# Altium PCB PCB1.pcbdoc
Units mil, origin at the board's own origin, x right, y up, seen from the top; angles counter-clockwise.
Board outline 3930 x 3935 mil, 2 copper layers (Top Layer, Bottom Layer); 17 components, 42 nets, 112 pads, 12 vias.
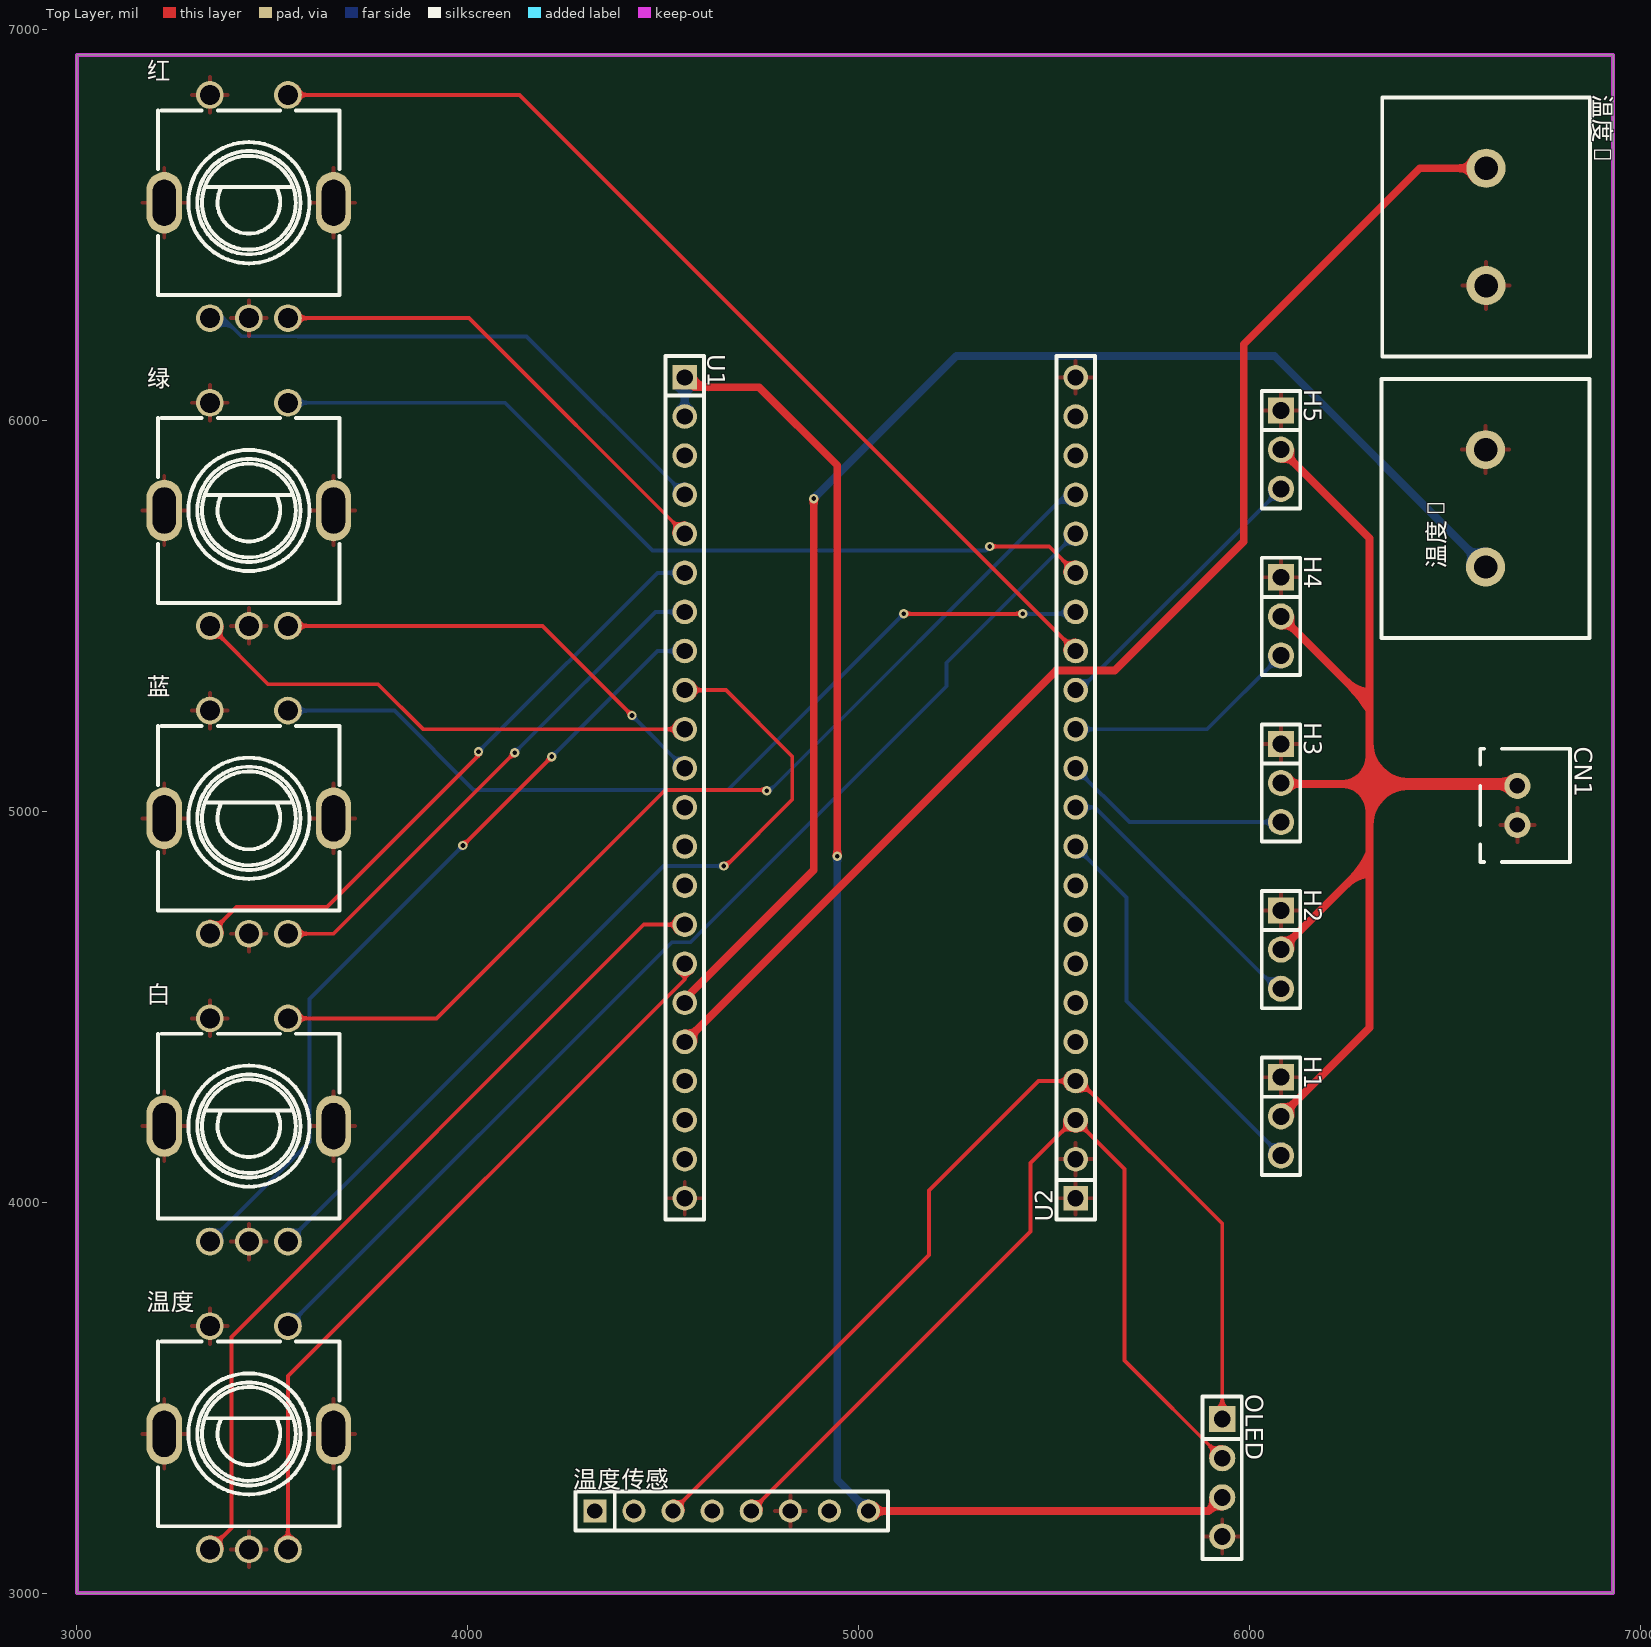
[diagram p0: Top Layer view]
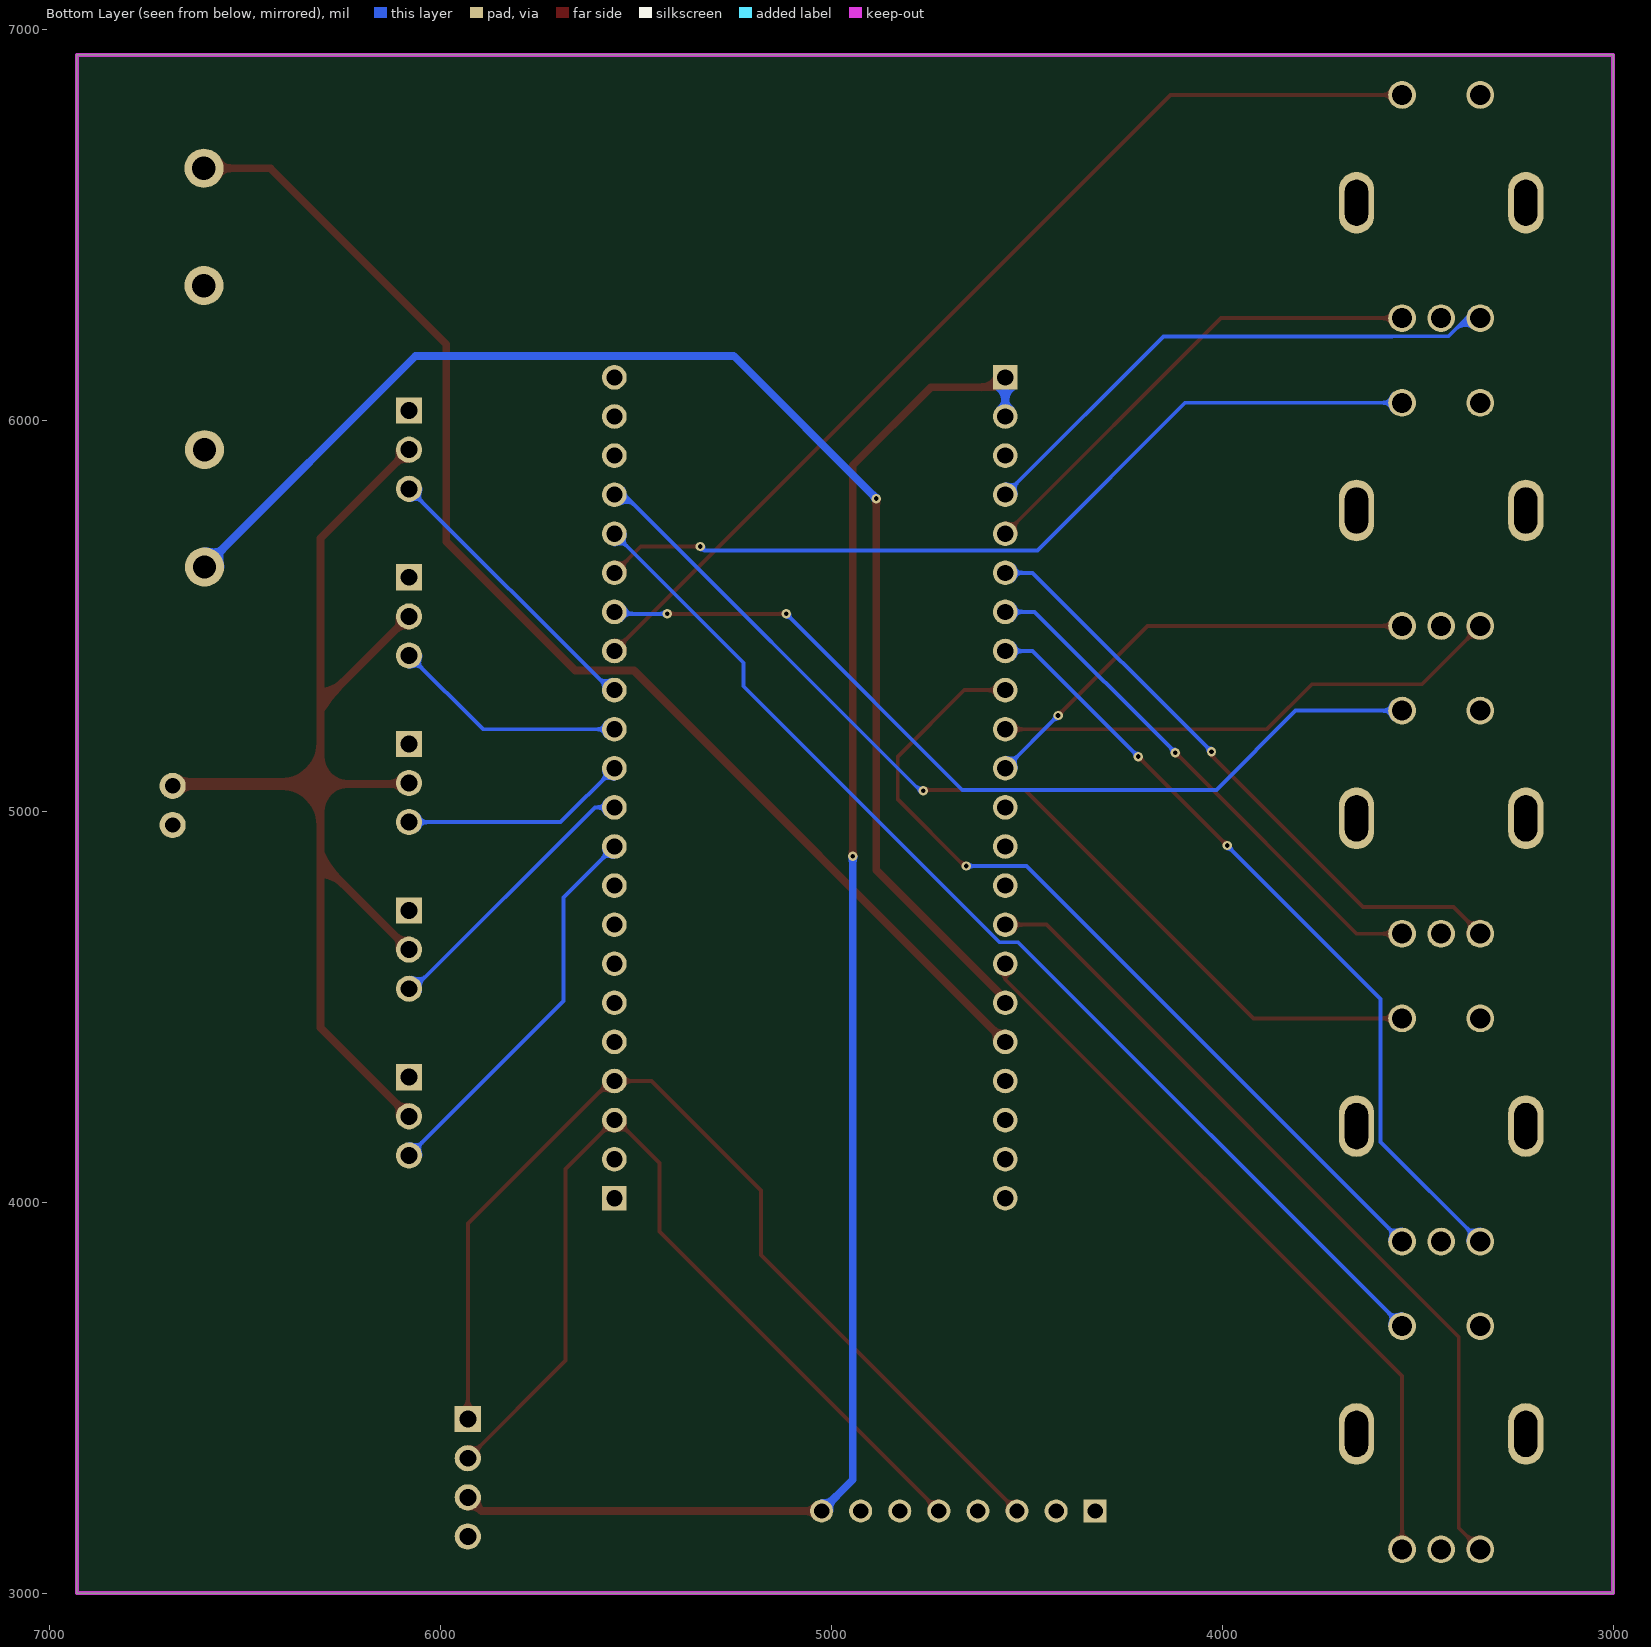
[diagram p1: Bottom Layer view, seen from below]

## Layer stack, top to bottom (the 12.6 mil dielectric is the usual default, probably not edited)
Top Layer: signal copper (thickness not stored)
Dielectric: dielectric 12.6, FR-4, Dk 4.8
Bottom Layer: signal copper (thickness not stored)

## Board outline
3000,6935 6930,6935 6930,3000 3000,3000

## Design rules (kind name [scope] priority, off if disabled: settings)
BoardOutlineClearance copperThickness1oz [All] p0: genericclearance=10 ignorepadtopadclearanceinfootprint=FALSE except(0: Arc-SplitContinuation Track-SplitContinuation SMDPad-SplitContinuation THPad-SplitContinuation Via-SplitContinuation Fill-SplitContinuation Poly-SplitContinuation Region-SplitContinuation Text-SplitContinuation; 6: Track-CutoutEdge SMDPad-CutoutEdge THPad-CutoutEdge Via-CutoutEdge Region-CutoutEdge; 11.8: Track-OutlineEdge SMDPad-OutlineEdge THPad-OutlineEdge Via-OutlineEdge Fill-OutlineEdge Region-OutlineEdge Poly-OutlineEdge Text-OutlineEdge Fill-CutoutEdge)
BoardOutlineClearance copperThickness2oz [All] p0: genericclearance=10 ignorepadtopadclearanceinfootprint=FALSE except(0: Arc-SplitContinuation Track-SplitContinuation SMDPad-SplitContinuation THPad-SplitContinuation Via-SplitContinuation Fill-SplitContinuation Poly-SplitContinuation Region-SplitContinuation Text-SplitContinuation; 6: Track-CutoutEdge SMDPad-CutoutEdge THPad-CutoutEdge Via-CutoutEdge Region-CutoutEdge; 11.8: Track-OutlineEdge SMDPad-OutlineEdge THPad-OutlineEdge Via-OutlineEdge Fill-OutlineEdge Region-OutlineEdge Poly-OutlineEdge Text-OutlineEdge Fill-CutoutEdge)
Clearance copperThickness1oz [(InNet('0') OR InNet('1') OR InNet('2') OR InNet('3') OR InNet('4') OR InNet('5') OR InNet('6') OR InNet('7') OR InNet('8') OR InNet('9') OR InNet('10') OR InNet('11') OR InNet('12') OR InNet('13') OR InNet('14') OR InNet('15') OR InNet('16') OR InNet('17') OR InNet('18') OR InNet('21') OR InNet('35') OR InNet('36') OR InNet('37') OR InNet('38') OR InNet('39') OR InNet('40') OR InNet('41') OR InNet('42') OR InNet('45') OR InNet('46') OR InNet('47') OR InNet('48') OR InNet('SDA') OR InNet('SCL') OR InNet('GND') OR InNet('3.3V') OR InNet('RST') OR InNet('5VIN') OR InNet('RX') OR InNet('TX') OR InNet('CS') OR InNet('+5V'))] p1: gap=7 ignorepadtopadclearanceinfootprint=FALSE except(4: Track-Track; 6: Track-SMDPad SMDPad-SMDPad Track-THPad SMDPad-THPad THPad-THPad Track-Via SMDPad-Via THPad-Via Via-Via SMDPad-Fill THPad-Fill Via-Fill Fill-Fill Track-Region SMDPad-Region THPad-Region Via-Region Region-Region Track-Poly SMDPad-Poly THPad-Poly Via-Poly Fill-Poly Region-Poly Poly-Poly Track-Text SMDPad-Text THPad-Text Via-Text Fill-Text Region-Text Poly-Text Text-Text; 6.9: Track-Hole SMDPad-Hole THPad-Hole Via-Hole Fill-Hole Region-Hole Poly-Hole Text-Hole Sheet-Hole; 11.8: Track-Fill Fill-Region Track-Sheet SMDPad-Sheet THPad-Sheet Via-Sheet Fill-Sheet Region-Sheet Poly-Sheet Text-Sheet)
Clearance copperThickness2oz [All] p1: gap=7 ignorepadtopadclearanceinfootprint=FALSE except(6: Track-SMDPad SMDPad-SMDPad Track-THPad SMDPad-THPad THPad-THPad Track-Via SMDPad-Via THPad-Via Via-Via SMDPad-Fill THPad-Fill Via-Fill Fill-Fill Track-Region SMDPad-Region THPad-Region Via-Region Region-Region Track-Poly SMDPad-Poly THPad-Poly Via-Poly Fill-Poly Region-Poly Poly-Poly Track-Text SMDPad-Text THPad-Text Via-Text Fill-Text Region-Text Poly-Text Text-Text; 6.9: Track-Hole SMDPad-Hole THPad-Hole Via-Hole Fill-Hole Region-Hole Poly-Hole Text-Hole Sheet-Hole; 8: Track-Track; 11.8: Track-Fill Fill-Region Track-Sheet SMDPad-Sheet THPad-Sheet Via-Sheet Fill-Sheet Region-Sheet Poly-Sheet Text-Sheet)
DiffPairsRouting differentialPair [All] p1: maxuncoupledlength=10 minlimit=6 maxlimit=6 mostfreqgap=6 toplayer_minwidth=5 toplayer_prefwidth=10 toplayer_maxwidth=100 bottomlayer_minwidth=5 bottomlayer_prefwidth=10 bottomlayer_maxwidth=100
PasteMaskExpansion pasteMaskExpansion [All] p1: expansion=0
PlaneConnect innerPlane [All] p1: planeconnectstyle=Relief reliefexpansion=20 reliefentries=4 reliefconductorwidth=10 reliefairgap=10
PolygonConnect copperRegion [All] p1: connectstyle=Relief reliefentries=4 reliefconductorwidth=10 polygonreliefangle="90 Angle" airgapwidth=10
RoutingVias viaSize [All] p1: viastyle="Through Hole" holewidth=12.0078 minholewidth=11.811 maxholewidth=248.0314 width=24.0158 minwidth=19.685 maxwidth=393.7008
SolderMaskExpansion solderMaskExpansion [All] p1: useseparateexpansions=TRUE expansion=2 expansionbottom=2
Width copperThickness1oz [All] p1: maxlimit=100 minlimit=5 preferedwidth=10
Width copperThickness2oz [All] p1: maxlimit=100 minlimit=8 preferedwidth=10

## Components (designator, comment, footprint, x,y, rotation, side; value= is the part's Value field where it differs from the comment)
CN1 "B2B-XH-A(LF)(SN)" CONN-TH_B2B-XH-A-LF-SN 6685,5015 r270 top
H1 "PZ254V-11-03P" HDR-TH_3P-P2.54-V-M 6080.28,4219.75 r270 top
H2 "PZ254V-11-03P" HDR-TH_3P-P2.54-V-M 6080.28,4646.06 r270 top
H3 "PZ254V-11-03P" HDR-TH_3P-P2.54-V-M 6080.28,5072.38 r270 top
H4 "PZ254V-11-03P" HDR-TH_3P-P2.54-V-M 6080.28,5498.69 r270 top
H5 "PZ254V-11-03P" HDR-TH_3P-P2.54-V-M 6080.28,5925 r270 top
OLED "HDR-F_2.54_1x4P" HDR-TH_4P-P2.54-V-F 5930,3295 r270 top
U1 "ZX-PM2.54-1-22PY" HDR-TH_22P-P2.54-V-F 4555,5060 r270 top
U2 "ZX-PM2.54-1-22PY" HDR-TH_22P-P2.54-V-F 5555,5060 r90 top
温度 "EC11E15244G1" SW-TH_EC11E15244G1 3440,3397.4 r0 top
温度1 "WJ25C-B-7.62-2P" CONN-TH_2P-P7.62_WJ25C-B-7.62-2P 6603.54,5775 r90 top
温度2 "WJ25C-B-7.62-2P" CONN-TH_2P-P7.62_WJ25C-B-7.62-2P 6605,6495 r270 top
温度传感 "PZ254V-11-08P" HDR-TH_8P-P2.54-V-M 4675,3210 r0 top
白 "EC11E15244G1" SW-TH_EC11E15244G1 3440,4184.8 r0 top
红 "5" SW-TH_EC11E15244G1 3440,6547.01 r0 top
绿 "EC11E15244G1" SW-TH_EC11E15244G1 3440,5759.61 r0 top
蓝 "EC11E15244G1" SW-TH_EC11E15244G1 3440,4972.2 r0 top

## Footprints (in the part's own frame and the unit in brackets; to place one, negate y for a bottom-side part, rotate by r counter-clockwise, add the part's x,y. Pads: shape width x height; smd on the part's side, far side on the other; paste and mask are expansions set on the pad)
CONN-TH_2P-P7.62_WJ25C-B-7.62-2P [mil]
  round 100 hole 60: 1(-150.1,0) 2(150.1,0)
  silkscreen extent -331,-266 331,266
CONN-TH_B2B-XH-A-LF-SN [mm]
  round 1.7 hole 1: 1(1.27,0) 2(-1.27,0)
  silkscreen extent -3.68,-2.41 3.68,3.43
HDR-TH_3P-P2.54-V-M [mm]
  rect 1.7x1.7 hole 1.1: 1(-2.54,0)
  round 1.7 hole 1.1: 2(0,0) 3(2.54,0)
  silkscreen extent -3.81,-1.25 3.81,1.25
HDR-TH_4P-P2.54-V-F [mm]
  rect 1.7x1.7 hole 1.1: 1(-3.81,0)
  round 1.7 hole 1.1: 2(-1.27,0) 3(1.27,0) 4(3.81,0)
  silkscreen extent -5.29,-1.27 5.29,1.27
HDR-TH_8P-P2.54-V-M [mm]
  rect 1.5x1.5 hole 1: 1(-8.89,0)
  round 1.5 hole 1: 2(-6.35,0) 3(-3.81,0) 4(-1.27,0) 5(1.27,0) 6(3.81,0) 7(6.35,0) 8(8.89,0)
  silkscreen extent -10.16,-1.27 10.16,1.27
HDR-TH_22P-P2.54-V-F [mm]
  rect 1.6x1.6 hole 1.05: 1(-26.67,0)
  round 1.6 hole 1.05: 2(-24.13,0) 3(-21.59,0) 4(-19.05,0) 5(-16.51,0) 6(-13.97,0) 7(-11.43,0) 8(-8.89,0) 9(-6.35,0) 10(-3.81,0) 11(-1.27,0) 12(1.27,0) 13(3.81,0) 14(6.35,0) 15(8.89,0) 16(11.43,0) 17(13.97,0) 18(16.51,0) 19(19.05,0) 20(21.59,0) 21(24.13,0) 22(26.67,0)
  silkscreen extent -28.06,-1.25 28.06,1.25
SW-TH_EC11E15244G1 [mm]
  oval 2.3x4 hole 1.5 slot 3 at 90 deg: 6(5.5,0.25) 7(-5.5,0.25)
  round 1.8 hole 1.3: A(-2.54,-7.25) B(2.54,-7.25) C(0,-7.25) D(-2.54,7.25) E(2.54,7.25)
  silkscreen extent -5.9,-5.75 5.9,6.25

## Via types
v1: diameter 24.02, hole 12.01, Top Layer to Bottom Layer, 12 vias

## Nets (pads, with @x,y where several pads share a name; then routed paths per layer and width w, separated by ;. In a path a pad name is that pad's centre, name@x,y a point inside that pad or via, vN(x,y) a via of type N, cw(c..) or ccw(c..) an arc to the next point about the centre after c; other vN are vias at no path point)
0: U2.9
1: U2.19 白.E | length 2572
  Top Layer w10: 白.E 3920.24,4470.24 4505,5055 4762.5,5055 v1(4765,5052.5)
  Bottom Layer w10: v1(4765,5052.5) 4772.5,5052.5 5530,5810 U2.19
2: U2.18 温度.E | length 2889.9
  Bottom Layer w10: 温度.E 4522.16,4665 4570.08,4665 5225,5319.92 5225,5380 U2.18
3: U1.13
3.3V: OLED.3 U1.1 U1.2 温度传感.8 | length 4210.8
  Top Layer w20: U1.1 4580,6085 4745,6085 4945,5885 v1(4945,4885) ; 温度传感.8 5895,3210 OLED.3
  Bottom Layer w20: U1.2 U1.1 ; v1(4945,4885) 4945,3290 温度传感.8
4: U1.4 红.A | length 1402.1
  Bottom Layer w10: 红.A 3374.35,6261.57 3420.77,6215.16 3564.84,6215.16 3565,6215 4150,6215 U1.4
5: U1.5 红.B | length 1243.5
  Top Layer w10: 红.B 4003.43,6261.57 U1.5
5VIN: U1.21
6: U1.6 蓝.A | length 1603.3
  Top Layer w10: 蓝.A 3408.23,4755 3640,4755 4027.5,5142.5 v1(4027.5,5152.5)
  Bottom Layer w10: v1(4027.5,5152.5) 4485,5610 U1.6
7: U1.7 蓝.B | length 1356
  Top Layer w10: 蓝.B 3656.77,4686.77 v1(4120,5150)
  Bottom Layer w10: v1(4120,5150) 4480,5510 U1.7
8: U1.12
9: U1.15 温度.A | length 2162.8
  Top Layer w10: 温度.A 3394.99,3166.97 3394.99,3654.99 4450,4710 U1.15
10: U1.16 温度.B | length 1918.5
  Top Layer w10: 温度.B 3539.99,3555.07 4555,4570.08 U1.16
11: U1.17 温度1.1 | length 3520.2
  Top Layer w20: U1.17 4555,4520 4884.9,4849.9 v1(4884.9,5800)
  Bottom Layer w20: v1(4884.9,5800) 4885,5800 5250,6165 6063.44,6165 温度1.1
12: U1.18 温度2.1 | length 3271.6
  Top Layer w20: U1.18 5505,5360 5655,5360 5985,5690 5985,6195 6435.1,6645.1 温度2.1
13: U1.19
14: U1.20
15: U1.8 白.A | length 2054.9
  Top Layer w10: v1(3987.5,4912.5) v1(4215,5140)
  Bottom Layer w10: 白.A 3595,4154.37 3595,4520 v1(3987.5,4912.5) ; v1(4215,5140) 4485,5410 U1.8
16: U1.9 白.B | length 2213.7
  Top Layer w10: U1.9 4660,5310 4830,5140 4830,5030 4660,4860 v1(4655,4860)
  Bottom Layer w10: 白.B 4500.63,4860 v1(4655,4860)
17: U1.10 绿.A | length 1324.4
  Top Layer w10: 绿.A 3489.17,5325 3770,5325 3885,5210 U1.10
18: U1.11 绿.B | length 1165.8
  Top Layer w10: 绿.B 4190.83,5474.17 v1(4420,5245)
  Bottom Layer w10: v1(4420,5245) U1.11
21: U2.5
35: H1.3 U2.10 | length 1007.8
  Bottom Layer w10: U2.10 5685,4780 5685,4515.03 H1.3
36: H2.3 U2.11 | length 717.4
  Bottom Layer w10: U2.11 5605,5010 6068.94,4546.06 H2.3
37: H3.3 U2.12 | length 582.3
  Bottom Layer w10: U2.12 5692.62,4972.38 H3.3
38: H4.3 U2.13 | length 603.4
  Bottom Layer w10: U2.13 5891.59,5210 H4.3
39: H5.3 U2.14 | length 738.6
  Bottom Layer w10: U2.14 5565.28,5310 H5.3
40: U2.15 红.E | length 2604.2
  Top Layer w10: 红.E 4132.56,6832.44 U2.15
41: U2.16 蓝.E | length 2287.4
  Top Layer w10: v1(5115,5505) v1(5420,5505)
  Bottom Layer w10: 蓝.E 3812.36,5257.64 4015,5055 4665,5055 v1(5115,5505) ; v1(5420,5505) 5550,5505 U2.16
42: U2.17 绿.E | length 2203.5
  Top Layer w10: v1(5335,5677.5) 5487.5,5677.5 U2.17
  Bottom Layer w10: 绿.E 4094.96,6045.04 4472.48,5667.52 5325.02,5667.52 v1(5335,5677.5)
45: U2.8
46: U1.14
47: U2.6
48: U2.7
+5V: CN1.2 H1.2 H2.2 H3.2 H4.2 H5.2 | length 3139.9
  Top Layer w20: H1.2 6306.8,4446.27 6306.8,4872.58 ; H2.2 6306.8,4872.58 ; H3.2 6082.65,5070 6306.8,5070 ; H4.2 6303.2,5275.77 6306.8,5275.77 ; H5.2 6306.8,5698.48 6306.8,5275.77 ; 6306.8,4872.58 6306.8,5070 ; 6306.8,5070 6306.8,5275.77
  Top Layer w30: 6306.8,5070 6680,5070 CN1.2
CS: 温度传感.2
GND: CN1.1 H1.1 H2.1 H3.1 H4.1 H5.1 OLED.4 U1.22 U2.1 U2.2 U2.22 温度1.2 温度2.2 温度.6 温度.7 温度.C 温度.D 温度传感.6 白.6 白.7 白.C 白.D 红.6 红.7 红.C 红.D 绿.6 绿.7 绿.C 绿.D 蓝.6 蓝.7 蓝.C 蓝.D
RST: U1.3
RX: U2.20
SCL: OLED.2 U2.3 温度传感.5 | length 2367.1
  Top Layer w10: 温度传感.5 5440,3925 5440,4100 5550,4210 U2.3 5680,4085 5680,3595 OLED.2
SDA: OLED.1 U2.4 温度传感.3 | length 2608.5
  Top Layer w10: 温度传感.3 5180,3865 5180,4030 5460,4310 U2.4 5565,4310 5930,3945 OLED.1
TX: U2.21
pads on no net: 温度传感.1 温度传感.4 温度传感.7

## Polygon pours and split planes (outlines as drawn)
GND on Top Layer (solid, remove dead copper, pour order 0): 3015,6915 6910,6915 6910,3015 3015,3015

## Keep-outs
Board Outline Layer:
  the board outline again, w10

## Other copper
Top Layer:
  region net SDA: 5925,3493.46 5935,3493.46 ccw(c5953.75,3493.46) 5942.5,3478.46 5917.5,3478.46 ccw(c5906.25,3493.46)
  region net SCL: 5894.25,3373.68 5901.32,3380.75 5903.27,3378.96 5905.1,3377.6 5906.85,3376.63 5908.53,3375.99 5910.16,3375.64 5911.78,3375.54 5913.4,3375.64 5915.05,3375.9 5922.4,3377.66 5926.86,3378.33 5929.37,3378.46 5932.1,3378.4 5896.6,3342.9 5896.54,3345.63 5896.67,3348.14 5897.34,3352.6 5899.1,3359.95 5899.36,3361.6 5899.46,3363.22 5899.36,3364.84 5899.01,3366.47 5898.37,3368.15 5897.4,3369.9 5896.04,3371.73
  region net 3.3V: 5904.86,3205.71 5890.71,3219.86 5892.1,3221.37 5893.25,3222.88 5894.19,3224.39 5894.94,3225.91 5895.51,3227.46 5895.93,3229.02 5896.42,3232.23 5896.55,3235.6 5896.51,3239.17 5896.47,3242.99 5896.6,3247.1 5932.1,3211.6 5927.99,3211.47 5924.17,3211.51 5920.6,3211.55 5917.23,3211.42 5914.02,3210.93 5912.46,3210.51 5910.91,3209.94 5909.39,3209.19 5907.88,3208.25 5906.37,3207.1
  region net 5: 3588.23,6266.57 3588.23,6256.57 3585.4,6256.45 3582.99,6256.09 3580.94,6255.51 3579.2,6254.72 3577.72,6253.74 3576.45,6252.59 3575.32,6251.28 3574.3,6249.83 3570.17,6242.92 3568.87,6240.99 3567.34,6239.02 3565.55,6237.02 3563.43,6235 3563.43,6288.15 3565.55,6286.13 3567.34,6284.12 3568.87,6282.15 3570.17,6280.23 3574.3,6273.31 3575.32,6271.86 3576.45,6270.56 3577.72,6269.4 3579.2,6268.43 3580.94,6267.64 3582.99,6267.06 3585.4,6266.7
  region net 40: 3588.23,6837.44 3588.23,6827.44 3585.4,6827.32 3582.99,6826.96 3580.94,6826.38 3579.2,6825.59 3577.72,6824.61 3576.45,6823.46 3575.32,6822.15 3574.3,6820.7 3570.17,6813.79 3568.87,6811.86 3567.34,6809.89 3565.55,6807.89 3563.43,6805.87 3563.43,6859.02 3565.55,6857 3567.34,6854.99 3568.87,6853.02 3570.17,6851.1 3574.3,6844.19 3575.32,6842.73 3576.45,6841.43 3577.72,6840.27 3579.2,6839.3 3580.94,6838.51 3582.99,6837.93 3585.4,6837.57
  region net 17: 3377.64,5443.6 3370.57,5436.53 3368.48,5438.44 3366.52,5439.89 3364.66,5440.93 3362.87,5441.6 3361.13,5441.96 3359.42,5442.05 3357.7,5441.91 3355.95,5441.61 3348.15,5439.64 3345.86,5439.21 3343.39,5438.89 3340.7,5438.74 3337.78,5438.81 3375.36,5476.39 3375.43,5473.47 3375.28,5470.78 3374.96,5468.31 3374.52,5466.02 3372.56,5458.21 3372.25,5456.47 3372.12,5454.75 3372.21,5453.03 3372.56,5451.3 3373.24,5449.51 3374.27,5447.65 3375.73,5445.69
  region net 18: 3588.23,5479.17 3588.23,5469.17 3585.4,5469.05 3582.99,5468.69 3580.94,5468.1 3579.2,5467.32 3577.72,5466.34 3576.45,5465.19 3575.32,5463.88 3574.3,5462.43 3570.17,5455.52 3568.87,5453.59 3567.34,5451.62 3565.55,5449.62 3563.43,5447.6 3563.43,5500.75 3565.55,5498.73 3567.34,5496.72 3568.87,5494.75 3570.17,5492.82 3574.3,5485.91 3575.32,5484.46 3576.45,5483.15 3577.72,5482 3579.2,5481.03 3580.94,5480.24 3582.99,5479.66 3585.4,5479.3
  region net 3.3V: 4616.5,6095 4616.5,6075 ccw(c4586.5,5948.33) 4586.5,6078.5 4586.5,6110 ccw(c4616.5,6132.5)
  region net 5: 4521.14,5736.79 4528.21,5743.86 4530.02,5742.2 4531.73,5740.93 4533.36,5740.01 4534.93,5739.4 4536.47,5739.06 4537.98,5738.95 4539.51,5739.02 4541.06,5739.24 4547.95,5740.78 4552.11,5741.38 4554.44,5741.5 4556.97,5741.43 4523.57,5708.03 4523.5,5710.56 4523.62,5712.89 4524.22,5717.05 4525.76,5723.94 4525.98,5725.49 4526.05,5727.02 4525.94,5728.53 4525.6,5730.07 4524.99,5731.64 4524.07,5733.27 4522.8,5734.98
  region net 16: 4597.88,5315 4597.88,5305 4595.43,5304.89 4593.32,5304.58 4591.52,5304.08 4589.98,5303.4 4588.66,5302.56 4587.5,5301.56 4586.48,5300.43 4585.54,5299.18 4581.75,5293.22 4579.23,5289.85 4577.67,5288.12 4575.83,5286.38 4575.83,5333.62 4577.67,5331.88 4579.23,5330.15 4581.75,5326.78 4585.54,5320.82 4586.48,5319.57 4587.5,5318.44 4588.66,5317.44 4589.98,5316.6 4591.52,5315.92 4593.32,5315.42 4595.43,5315.11
  region net 17: 4512.12,5205 4512.12,5215 4514.57,5215.11 4516.68,5215.42 4518.48,5215.92 4520.02,5216.6 4521.34,5217.44 4522.5,5218.44 4523.52,5219.57 4524.46,5220.82 4528.25,5226.78 4530.77,5230.15 4532.33,5231.88 4534.17,5233.62 4534.17,5186.38 4532.33,5188.12 4530.77,5189.85 4528.25,5193.22 4524.46,5199.18 4523.52,5200.43 4522.5,5201.56 4521.34,5202.56 4520.02,5203.4 4518.48,5204.08 4516.68,5204.58 4514.57,5204.89
  region net 9: 4512.12,4705 4512.12,4715 4514.57,4715.11 4516.68,4715.42 4518.48,4715.92 4520.02,4716.6 4521.34,4717.44 4522.5,4718.44 4523.52,4719.57 4524.46,4720.82 4528.25,4726.78 4530.77,4730.15 4532.33,4731.88 4534.17,4733.62 4534.17,4686.38 4532.33,4688.12 4530.77,4689.85 4528.25,4693.22 4524.46,4699.18 4523.52,4700.43 4522.5,4701.56 4521.34,4702.56 4520.02,4703.4 4518.48,4704.08 4516.68,4704.58 4514.57,4704.89
  region net 10: 4560,4570.08 4550,4570.08 4549.84,4571.39 4549.39,4572.7 4548.68,4574 4547.74,4575.29 4545.34,4577.82 4542.43,4580.28 4536.25,4584.95 4533.51,4587.12 4531.38,4589.17 4578.62,4589.17 4576.49,4587.12 4573.75,4584.95 4567.57,4580.28 4564.66,4577.82 4562.26,4575.29 4561.32,4574 4560.61,4572.7 4560.16,4571.39
  region net 12: 4578.25,4447.39 4592.39,4433.25 4591.13,4431.88 4590.07,4430.5 4589.19,4429.1 4588.48,4427.68 4587.48,4424.78 4586.92,4421.76 4586.68,4418.6 4586.61,4415.28 4586.43,4408.03 4553.03,4441.43 4560.28,4441.61 4563.6,4441.68 4566.76,4441.92 4569.78,4442.48 4572.68,4443.48 4574.1,4444.19 4575.5,4445.07 4576.88,4446.13
  region net SCL: 5523.93,4176.86 5520.61,4187.68 5521.51,4188.79 5522.23,4190.1 5522.79,4191.59 5523.2,4193.23 5523.68,4196.87 5523.8,4200.8 5523.65,4208.76 5523.68,4212.38 5523.99,4215.49 5553.43,4178.54 5548.74,4179.05 5544.55,4179.88 5540.75,4180.77 5537.23,4181.47 5535.55,4181.65 5533.9,4181.69 5532.26,4181.54 5530.64,4181.17 5529,4180.56 5527.35,4179.65 5525.66,4178.43
  region net SCL: 5588.86,4183.21 5581.79,4176.14 5579.98,4177.8 5578.27,4179.07 5576.64,4179.99 5575.07,4180.6 5573.53,4180.94 5572.02,4181.05 5570.49,4180.98 5568.94,4180.76 5562.05,4179.22 5557.89,4178.62 5555.56,4178.5 5553.03,4178.57 5586.43,4211.97 5586.5,4209.44 5586.38,4207.11 5585.78,4202.95 5584.24,4196.06 5584.02,4194.51 5583.95,4192.98 5584.06,4191.47 5584.4,4189.93 5585.01,4188.36 5585.93,4186.73 5587.2,4185.02
  region net SDA: 5512.12,4305 5512.12,4315 5514.57,4315.11 5516.68,4315.42 5518.48,4315.92 5520.02,4316.6 5521.34,4317.44 5522.5,4318.44 5523.52,4319.57 5524.46,4320.82 5528.25,4326.78 5530.77,4330.15 5532.33,4331.88 5534.17,4333.62 5534.17,4286.38 5532.33,4288.12 5530.77,4289.85 5528.25,4293.22 5524.46,4299.18 5523.52,4300.43 5522.5,4301.56 5521.34,4302.56 5520.02,4303.4 5518.48,4304.08 5516.68,4304.58 5514.57,4304.89
  region net SDA: 5589.73,4292.34 5590.16,4277.77 5588.49,4279.27 5586.83,4280.45 5585.15,4281.35 5583.46,4281.98 5581.76,4282.38 5580.02,4282.58 5578.26,4282.59 5576.46,4282.44 5572.74,4281.8 5568.8,4280.86 5564.62,4279.83 5560.14,4278.93 5585.19,4318.98 5585.82,4315.81 5586.07,4312.32 5586.16,4304.89 5586.36,4301.25 5586.9,4297.84 5587.36,4296.28 5587.97,4294.83 5588.75,4293.51
  region net 40: 5521.14,5436.79 5528.21,5443.86 5530.02,5442.2 5531.73,5440.93 5533.36,5440.01 5534.93,5439.4 5536.47,5439.06 5537.98,5438.95 5539.51,5439.02 5541.06,5439.24 5547.95,5440.78 5552.11,5441.38 5554.44,5441.5 5556.97,5441.43 5523.57,5408.03 5523.5,5410.56 5523.62,5412.89 5524.22,5417.05 5525.76,5423.94 5525.98,5425.49 5526.05,5427.02 5525.94,5428.53 5525.6,5430.07 5524.99,5431.64 5524.07,5433.27 5522.8,5434.98
  region net 42: 5521.14,5636.79 5528.21,5643.86 5530.02,5642.2 5531.73,5640.93 5533.36,5640.01 5534.93,5639.4 5536.47,5639.06 5537.98,5638.95 5539.51,5639.02 5541.06,5639.24 5547.95,5640.78 5552.11,5641.38 5554.44,5641.5 5556.97,5641.43 5523.57,5608.03 5523.5,5610.56 5523.62,5612.89 5524.22,5617.05 5525.76,5623.94 5525.98,5625.49 5526.05,5627.02 5525.94,5628.53 5525.6,5630.07 5524.99,5631.64 5524.07,5633.27 5522.8,5634.98
  region net 9: 3370.57,3149.61 3377.64,3142.54 3375.73,3140.45 3374.27,3138.49 3373.24,3136.63 3372.56,3134.84 3372.21,3133.1 3372.12,3131.39 3372.25,3129.67 3372.56,3127.92 3374.52,3120.12 3374.96,3117.83 3375.28,3115.36 3375.43,3112.67 3375.36,3109.75 3337.78,3147.33 3340.7,3147.4 3343.39,3147.25 3345.86,3146.93 3348.15,3146.5 3355.95,3144.53 3357.7,3144.23 3359.42,3144.09 3361.13,3144.18 3362.87,3144.53 3364.66,3145.21 3366.52,3146.25 3368.48,3147.7
  region net 10: 3534.99,3160.21 3544.99,3160.21 3545.12,3157.37 3545.48,3154.96 3546.06,3152.91 3546.85,3151.17 3547.83,3149.69 3548.98,3148.42 3550.29,3147.3 3551.74,3146.28 3558.65,3142.15 3560.57,3140.84 3562.55,3139.31 3564.55,3137.52 3566.57,3135.4 3513.42,3135.4 3515.44,3137.52 3517.44,3139.31 3519.42,3140.84 3521.34,3142.15 3528.25,3146.28 3529.7,3147.3 3531.01,3148.42 3532.16,3149.69 3533.14,3151.17 3533.93,3152.91 3534.51,3154.96 3534.87,3157.37
  region net SDA: 4549.89,3241.96 4556.96,3234.89 4555.43,3233.22 4554.26,3231.64 4553.4,3230.13 4552.82,3228.66 4552.49,3227.23 4552.36,3225.81 4552.58,3222.93 4553.91,3216.5 4554.43,3212.64 4554.53,3210.48 4554.47,3208.15 4523.15,3239.47 4525.48,3239.53 4527.64,3239.43 4531.5,3238.91 4537.93,3237.58 4540.81,3237.36 4542.23,3237.49 4543.66,3237.82 4545.13,3238.4 4546.64,3239.26 4548.22,3240.43
  region net SCL: 4749.89,3241.96 4756.96,3234.89 4755.43,3233.22 4754.26,3231.64 4753.4,3230.13 4752.82,3228.66 4752.49,3227.23 4752.36,3225.81 4752.58,3222.93 4753.91,3216.5 4754.43,3212.64 4754.53,3210.48 4754.47,3208.15 4723.15,3239.47 4725.48,3239.53 4727.64,3239.43 4731.5,3238.91 4737.93,3237.58 4740.81,3237.36 4742.23,3237.49 4743.66,3237.82 4745.13,3238.4 4746.64,3239.26 4748.22,3240.43
  region net 3.3V: 5065.2,3220 5065.2,3200 5061.96,3199.73 5059.07,3198.96 5056.44,3197.76 5054,3196.2 5051.68,3194.37 5049.37,3192.31 5044.53,3187.85 5044.53,3232.15 5049.37,3227.69 5051.68,3225.63 5054,3223.8 5056.44,3222.24 5059.07,3221.04 5061.96,3220.27
  region net 1: 3588.23,4475.24 3588.23,4465.24 3585.4,4465.11 3582.99,4464.75 3580.94,4464.17 3579.2,4463.38 3577.72,4462.41 3576.45,4461.26 3575.32,4459.95 3574.3,4458.5 3570.17,4451.59 3568.87,4449.66 3567.34,4447.69 3565.55,4445.68 3563.43,4443.66 3563.43,4496.81 3565.55,4494.79 3567.34,4492.79 3568.87,4490.82 3570.17,4488.89 3574.3,4481.98 3575.32,4480.53 3576.45,4479.22 3577.72,4478.07 3579.2,4477.09 3580.94,4476.3 3582.99,4475.72 3585.4,4475.36
  region net 6: 3370.57,4724.42 3377.64,4717.34 3375.73,4715.26 3374.27,4713.29 3373.24,4711.43 3372.56,4709.64 3372.21,4707.91 3372.12,4706.19 3372.25,4704.47 3372.56,4702.73 3374.52,4694.92 3374.96,4692.63 3375.28,4690.16 3375.43,4687.47 3375.36,4684.55 3337.78,4722.13 3340.7,4722.2 3343.39,4722.05 3345.86,4721.73 3348.15,4721.3 3355.95,4719.33 3357.7,4719.03 3359.42,4718.9 3361.13,4718.98 3362.87,4719.34 3364.66,4720.01 3366.52,4721.05 3368.48,4722.5
  region net 7: 3588.23,4691.77 3588.23,4681.77 3585.4,4681.65 3582.99,4681.29 3580.94,4680.7 3579.2,4679.92 3577.72,4678.94 3576.45,4677.79 3575.32,4676.48 3574.3,4675.03 3570.17,4668.12 3568.87,4666.19 3567.34,4664.22 3565.55,4662.21 3563.43,4660.19 3563.43,4713.34 3565.55,4711.32 3567.34,4709.32 3568.87,4707.35 3570.17,4705.42 3574.3,4698.51 3575.32,4697.06 3576.45,4695.75 3577.72,4694.6 3579.2,4693.62 3580.94,4692.84 3582.99,4692.25 3585.4,4691.89
  region net +5V: 6635.94,5055 6643.44,5085 6646.34,5085.18 6649.38,5085.7 6652.48,5086.5 6655.6,5087.54 6658.66,5088.77 6661.6,5090.14 6664.36,5091.61 6666.86,5093.12 6659.36,5043.49 6657.28,5045.64 6654.72,5047.72 6651.81,5049.66 6648.66,5051.4 6645.38,5052.88 6642.09,5054.01 6638.9,5054.74
  region net +5V: 6105.42,4259.04 6119.57,4244.9 6118.18,4243.38 6117.03,4241.88 6116.09,4240.36 6115.34,4238.84 6114.77,4237.3 6114.35,4235.73 6113.86,4232.52 6113.73,4229.15 6113.76,4225.58 6113.81,4221.77 6113.68,4217.66 6078.18,4253.15 6082.29,4253.28 6086.11,4253.24 6089.68,4253.2 6093.05,4253.34 6096.26,4253.82 6097.82,4254.24 6099.36,4254.81 6100.89,4255.56 6102.4,4256.5 6103.91,4257.65
  region net +5V: 6105.42,4685.35 6119.57,4671.21 6118.18,4669.7 6117.03,4668.19 6116.09,4666.67 6115.34,4665.15 6114.77,4663.61 6114.35,4662.05 6113.86,4658.83 6113.73,4655.46 6113.76,4651.89 6113.81,4648.08 6113.68,4643.97 6078.18,4679.46 6082.29,4679.59 6086.11,4679.55 6089.68,4679.51 6093.05,4679.65 6096.26,4680.13 6097.82,4680.55 6099.36,4681.13 6100.89,4681.87 6102.4,4682.81 6103.91,4683.96
  region net +5V: 6127.57,5080 6124,5060 6121.91,5059.92 6120.01,5059.68 6118.28,5059.3 6116.7,5058.78 6115.25,5058.13 6113.89,5057.37 6111.39,5055.55 6108.99,5053.4 6106.52,5050.99 6103.78,5048.42 6100.58,5045.77 6104.14,5095.84 6109.52,5090.02 6112.05,5087.35 6114.61,5084.95 6117.33,5082.92 6118.78,5082.08 6120.31,5081.36 6121.95,5080.78 6123.69,5080.36 6125.56,5080.09
  region net +5V: 6119.57,5473.54 6105.42,5459.4 6103.91,5460.79 6102.4,5461.94 6100.89,5462.88 6099.36,5463.63 6097.82,5464.2 6096.26,5464.62 6093.05,5465.1 6089.68,5465.24 6086.11,5465.2 6082.29,5465.16 6078.18,5465.29 6113.68,5500.78 6113.81,5496.67 6113.76,5492.86 6113.73,5489.29 6113.86,5485.92 6114.35,5482.71 6114.77,5481.14 6115.34,5479.6 6116.09,5478.08 6117.03,5476.56 6118.18,5475.05
  region net +5V: 6119.57,5899.86 6105.42,5885.71 6103.91,5887.1 6102.4,5888.25 6100.89,5889.19 6099.36,5889.94 6097.82,5890.51 6096.26,5890.93 6093.05,5891.42 6089.68,5891.55 6086.11,5891.51 6082.29,5891.47 6078.18,5891.6 6113.68,5927.1 6113.81,5922.99 6113.76,5919.17 6113.73,5915.6 6113.86,5912.23 6114.35,5909.02 6114.77,5907.46 6115.34,5905.91 6116.09,5904.39 6117.03,5902.88 6118.18,5901.37
  region net 12: 6536.93,6635.1 6536.93,6655.1 6540.58,6655.26 6543.76,6655.72 6546.54,6656.46 6548.97,6657.46 6551.12,6658.71 6553.03,6660.18 6554.76,6661.84 6556.38,6663.69 6559.48,6667.86 6562.81,6672.5 6564.69,6674.96 6566.8,6677.47 6569.19,6680.03 6571.93,6682.6 6571.93,6607.6 6569.19,6610.17 6566.8,6612.73 6564.69,6615.24 6562.81,6617.7 6559.48,6622.34 6556.38,6626.51 6554.76,6628.36 6553.03,6630.02 6551.12,6631.49 6548.97,6632.74 6546.54,6633.74 6543.76,6634.48 6540.58,6634.94
  region net 7: 4111.98,5134.9 4104.9,5141.98 4105.65,5142.84 4106.27,5143.83 4107.19,5146.03 4107.75,5148.41 4108.02,5150.75 4120.75,5138.02 4118.41,5137.75 4116.03,5137.19 4113.83,5136.27 4112.84,5135.65
  region net 6: 4029.3,5137.23 4014.65,5136.72 4016.59,5138.81 4017.41,5139.88 4018.05,5140.97 4018.45,5142.08 4018.57,5143.22 4018.34,5144.37 4017.72,5145.54 4035.16,5143.26 4033.71,5141.91 4032.18,5140.31
  region net 1: 4746.95,5050 4750.7,5060 4752.92,5060.25 4755.05,5060.93 4757.11,5061.87 4759.11,5062.96 4755.36,5045.35 4753.72,5047.05 4751.59,5048.55 4749.24,5049.6 4748.07,5049.9
  region net 15: 3995.52,4927.6 4002.6,4920.52 4001.85,4919.66 4001.23,4918.67 4000.31,4916.47 3999.75,4914.09 3999.48,4911.75 3986.75,4924.48 3989.09,4924.75 3991.47,4925.31 3993.67,4926.23 3994.66,4926.85
  region net 15: 4206.98,5124.9 4199.9,5131.98 4200.65,5132.84 4201.27,5133.83 4202.19,5136.03 4202.75,5138.41 4203.02,5140.75 4215.75,5128.02 4213.41,5127.75 4211.03,5127.19 4208.83,5126.27 4207.84,5125.65
  region net 16: 4667.15,4874.22 4670.47,4863.4 4669.08,4861.72 4667.96,4859.83 4667.04,4857.81 4666.23,4855.75 4657.81,4871.67 4658.92,4871.51 4660.14,4871.51 4662.76,4871.95 4665.24,4872.89 4666.29,4873.51
  region net 11: 4894.9,5785.59 4874.9,5785.59 4874.81,5788.24 4874.59,5790.74 4873.9,5795.12 4873.21,5798.34 4872.89,5800 4896.91,5800 4896.59,5798.34 4895.9,5795.12 4895.21,5790.74 4894.99,5788.24
  region net 3.3V: 4935,4899.41 4955,4899.41 4955.09,4896.76 4955.31,4894.26 4956,4889.88 4956.69,4886.66 4957.01,4885 4932.99,4885 4933.31,4886.66 4934,4889.88 4934.69,4894.26 4934.91,4896.76
  region net 42: 5351.35,5682.5 5351.35,5672.5 5350.21,5672.41 5349.08,5672.16 5346.86,5671.25 5344.79,5669.97 5342.94,5668.49 5342.94,5686.51 5344.79,5685.03 5346.86,5683.75 5349.08,5682.84 5350.21,5682.59
  region net 18: 4404.9,5253.02 4411.98,5260.1 4412.84,5259.35 4413.83,5258.73 4416.03,5257.81 4418.41,5257.25 4420.75,5256.98 4408.02,5244.25 4407.75,5246.59 4407.19,5248.97 4406.27,5251.17 4405.65,5252.16
  region net 41: 5131.35,5510 5131.35,5500 5130.21,5499.91 5129.08,5499.66 5126.86,5498.75 5124.79,5497.47 5122.94,5495.99 5122.94,5514.01 5124.79,5512.53 5126.86,5511.25 5129.08,5510.34 5130.21,5510.09
  region net 41: 5403.65,5500 5403.65,5510 5404.79,5510.09 5405.92,5510.34 5408.14,5511.25 5410.21,5512.53 5412.06,5514.01 5412.06,5495.99 5410.21,5497.47 5408.14,5498.75 5405.92,5499.66 5404.79,5499.91
  region net +5V: 6236.8,5060 cw(c6236.8,5000) 6296.8,5000 6316.8,4965 cw(c6406.8,4965) 6406.8,5055 6406.8,5085 cw(c6406.8,5175) 6316.8,5175 6296.8,5140 cw(c6236.8,5140) 6236.8,5080
  region net +5V: 6253.7,5311.12 cw(c6052.99,5110.41) 6296.8,5255.77 6306.8,5275.77 6296.8,5316.31 cw(c6311.94,5396.31) 6254.37,5338.74
  region net +5V: 6254.37,4834.3 ccw(c6111.94,4976.72) 6296.8,4896.72 6306.8,4872.58 6296.8,4828.44 ccw(c6311.94,4748.44) 6254.37,4806.01
Bottom Layer:
  region net 4: 3377.89,6265.11 3396.15,6232.7 3394.53,6234.15 3392.75,6235.43 3390.82,6236.55 3388.77,6237.49 3386.62,6238.27 3384.39,6238.86 3382.11,6239.28 3379.81,6239.52 3377.49,6239.58 3375.19,6239.45 3372.93,6239.13 3370.73,6238.63 3368.62,6237.92 3366.61,6237.02 3364.73,6235.92 3363,6234.62 3364.22,6287.43 3365.84,6285.81 3367.17,6284.29 3369.08,6281.47 3370.3,6278.88 3371.16,6276.39 3372.01,6273.88 3373.19,6271.24 3375.03,6268.36 3376.31,6266.79
  region net 42: 3588.23,6050.04 3588.23,6040.04 3585.4,6039.92 3582.99,6039.56 3580.94,6038.97 3579.2,6038.19 3577.72,6037.21 3576.45,6036.06 3575.32,6034.75 3574.3,6033.3 3570.17,6026.39 3568.87,6024.46 3567.34,6022.49 3565.55,6020.49 3563.43,6018.47 3563.43,6071.62 3565.55,6069.6 3567.34,6067.59 3568.87,6065.62 3570.17,6063.69 3574.3,6056.78 3575.32,6055.33 3576.45,6054.02 3577.72,6052.87 3579.2,6051.9 3580.94,6051.11 3582.99,6050.53 3585.4,6050.17
  region net 3.3V: 4565,6048.5 4545,6048.5 ccw(c4507.5,6048.5) 4530,6078.5 4580,6078.5 ccw(c4602.5,6048.5)
  region net 3.3V: 4545,6052.88 4565,6052.88 4565.08,6051.02 4565.31,6049.29 4565.67,6047.68 4566.17,6046.18 4567.51,6043.42 4569.26,6040.89 4571.32,6038.49 4573.62,6036.09 4578.62,6030.83 4531.38,6030.83 4536.38,6036.09 4538.68,6038.49 4540.74,6040.89 4542.49,6043.42 4543.83,6046.18 4544.33,6047.68 4544.69,6049.29 4544.92,6051.02
  region net 4: 4521.14,5836.79 4528.21,5843.86 4530.02,5842.2 4531.73,5840.93 4533.36,5840.01 4534.93,5839.4 4536.47,5839.06 4537.98,5838.95 4539.51,5839.02 4541.06,5839.24 4547.95,5840.78 4552.11,5841.38 4554.44,5841.5 4556.97,5841.43 4523.57,5808.03 4523.5,5810.56 4523.62,5812.89 4524.22,5817.05 4525.76,5823.94 4525.98,5825.49 4526.05,5827.02 4525.94,5828.53 4525.6,5830.07 4524.99,5831.64 4524.07,5833.27 4522.8,5834.98
  region net 6: 4512.12,5605 4512.12,5615 4514.57,5615.11 4516.68,5615.42 4518.48,5615.92 4520.02,5616.6 4521.34,5617.44 4522.5,5618.44 4523.52,5619.57 4524.46,5620.82 4528.25,5626.78 4530.77,5630.15 4532.33,5631.88 4534.17,5633.62 4534.17,5586.38 4532.33,5588.12 4530.77,5589.85 4528.25,5593.22 4524.46,5599.18 4523.52,5600.43 4522.5,5601.56 4521.34,5602.56 4520.02,5603.4 4518.48,5604.08 4516.68,5604.58 4514.57,5604.89
  region net 7: 4512.12,5505 4512.12,5515 4514.57,5515.11 4516.68,5515.42 4518.48,5515.92 4520.02,5516.6 4521.34,5517.44 4522.5,5518.44 4523.52,5519.57 4524.46,5520.82 4528.25,5526.78 4530.77,5530.15 4532.33,5531.88 4534.17,5533.62 4534.17,5486.38 4532.33,5488.12 4530.77,5489.85 4528.25,5493.22 4524.46,5499.18 4523.52,5500.43 4522.5,5501.56 4521.34,5502.56 4520.02,5503.4 4518.48,5504.08 4516.68,5504.58 4514.57,5504.89
  region net 15: 4512.12,5405 4512.12,5415 4514.57,5415.11 4516.68,5415.42 4518.48,5415.92 4520.02,5416.6 4521.34,5417.44 4522.5,5418.44 4523.52,5419.57 4524.46,5420.82 4528.25,5426.78 4530.77,5430.15 4532.33,5431.88 4534.17,5433.62 4534.17,5386.38 4532.33,5388.12 4530.77,5389.85 4528.25,5393.22 4524.46,5399.18 4523.52,5400.43 4522.5,5401.56 4521.34,5402.56 4520.02,5403.4 4518.48,5404.08 4516.68,5404.58 4514.57,5404.89
  region net 18: 4521.14,5136.79 4528.21,5143.86 4530.02,5142.2 4531.73,5140.93 4533.36,5140.01 4534.93,5139.4 4536.47,5139.06 4537.98,5138.95 4539.51,5139.02 4541.06,5139.24 4547.95,5140.78 4552.11,5141.38 4554.44,5141.5 4556.97,5141.43 4523.57,5108.03 4523.5,5110.56 4523.62,5112.89 4524.22,5117.05 4525.76,5123.94 4525.98,5125.49 4526.05,5127.02 4525.94,5128.53 4525.6,5130.07 4524.99,5131.64 4524.07,5133.27 4522.8,5134.98
  region net 35: 5588.86,4883.21 5581.79,4876.14 5579.98,4877.8 5578.27,4879.07 5576.64,4879.99 5575.07,4880.6 5573.53,4880.94 5572.02,4881.05 5570.49,4880.98 5568.94,4880.76 5562.05,4879.22 5557.89,4878.62 5555.56,4878.5 5553.03,4878.57 5586.43,4911.97 5586.5,4909.44 5586.38,4907.11 5585.78,4902.95 5584.24,4896.06 5584.02,4894.51 5583.95,4892.98 5584.06,4891.47 5584.4,4889.93 5585.01,4888.36 5585.93,4886.73 5587.2,4885.02
  region net 36: 5597.88,5015 5597.88,5005 5595.43,5004.89 5593.32,5004.58 5591.52,5004.08 5589.98,5003.4 5588.66,5002.56 5587.5,5001.56 5586.48,5000.43 5585.54,4999.18 5581.75,4993.22 5579.23,4989.85 5577.67,4988.12 5575.83,4986.38 5575.83,5033.62 5577.67,5031.88 5579.23,5030.15 5581.75,5026.78 5585.54,5020.82 5586.48,5019.57 5587.5,5018.44 5588.66,5017.44 5589.98,5016.6 5591.52,5015.92 5593.32,5015.42 5595.43,5015.11
  region net 37: 5588.86,5083.21 5581.79,5076.14 5579.98,5077.8 5578.27,5079.07 5576.64,5079.99 5575.07,5080.6 5573.53,5080.94 5572.02,5081.05 5570.49,5080.98 5568.94,5080.76 5562.05,5079.22 5557.89,5078.62 5555.56,5078.5 5553.03,5078.57 5586.43,5111.97 5586.5,5109.44 5586.38,5107.11 5585.78,5102.95 5584.24,5096.06 5584.02,5094.51 5583.95,5092.98 5584.06,5091.47 5584.4,5089.93 5585.01,5088.36 5585.93,5086.73 5587.2,5085.02
  region net 38: 5597.88,5215 5597.88,5205 5595.43,5204.89 5593.32,5204.58 5591.52,5204.08 5589.98,5203.4 5588.66,5202.56 5587.5,5201.56 5586.48,5200.43 5585.54,5199.18 5581.75,5193.22 5579.23,5189.85 5577.67,5188.12 5575.83,5186.38 5575.83,5233.62 5577.67,5231.88 5579.23,5230.15 5581.75,5226.78 5585.54,5220.82 5586.48,5219.57 5587.5,5218.44 5588.66,5217.44 5589.98,5216.6 5591.52,5215.92 5593.32,5215.42 5595.43,5215.11
  region net 39: 5590.38,5342.17 5589.74,5327.39 5588.76,5326.22 5587.97,5324.9 5587.36,5323.45 5586.9,5321.89 5586.35,5318.5 5586.15,5314.88 5586.04,5307.49 5585.78,5303.99 5585.13,5300.83 5560.34,5341.04 5564.81,5340.12 5568.99,5339.08 5572.93,5338.13 5576.67,5337.49 5578.47,5337.35 5580.24,5337.37 5581.98,5337.56 5583.69,5337.96 5585.38,5338.6 5587.06,5339.5 5588.72,5340.68
  region net 41: 5516.13,5500 5508.63,5510 5510.93,5510.11 5512.97,5510.45 5514.78,5510.99 5516.39,5511.72 5517.83,5512.63 5519.13,5513.69 5520.32,5514.91 5521.43,5516.25 5523.5,5519.28 5525.58,5522.67 5527.9,5526.28 5530.68,5530.02 5538.18,5483.37 5535.66,5485.28 5533.05,5487.72 5527.61,5493.24 5524.8,5495.83 5521.94,5497.99 5520.5,5498.82 5519.05,5499.46 5517.59,5499.86
  region net 2: 5528.21,5676.14 5521.14,5683.21 5522.8,5685.02 5524.07,5686.73 5524.99,5688.36 5525.6,5689.93 5525.94,5691.47 5526.05,5692.98 5525.98,5694.51 5525.76,5696.06 5524.22,5702.95 5523.62,5707.11 5523.5,5709.44 5523.57,5711.97 5556.97,5678.57 5554.44,5678.5 5552.11,5678.62 5547.95,5679.22 5541.06,5680.76 5539.51,5680.98 5537.98,5681.05 5536.47,5680.94 5534.93,5680.6 5533.36,5679.99 5531.73,5679.07 5530.02,5677.8
  region net 1: 5508.88,5781.81 5520.56,5807.63 5521.96,5809.15 5523.07,5810.58 5523.92,5811.93 5524.56,5813.22 5525.34,5815.69 5525.75,5818.08 5526.1,5820.52 5526.72,5823.12 5527.24,5824.52 5527.95,5826 5528.88,5827.58 5530.09,5829.28 5538.99,5782.88 5535.38,5784.69 5531.49,5786.04 5527.43,5786.88 5523.32,5787.18 5521.29,5787.1 5519.29,5786.86 5517.35,5786.46 5515.46,5785.9 5513.66,5785.15 5511.95,5784.23 5510.35,5783.11
  region net 2: 3570.57,3720.48 3577.64,3713.41 3575.73,3711.32 3574.27,3709.36 3573.24,3707.5 3572.56,3705.71 3572.21,3703.97 3572.12,3702.26 3572.25,3700.54 3572.56,3698.79 3574.52,3690.99 3574.96,3688.7 3575.28,3686.23 3575.43,3683.54 3575.36,3680.62 3537.78,3718.2 3540.7,3718.27 3543.39,3718.12 3545.86,3717.8 3548.15,3717.37 3555.95,3715.4 3557.7,3715.1 3559.42,3714.96 3561.13,3715.05 3562.87,3715.4 3564.66,3716.08 3566.52,3717.12 3568.48,3718.57
  region net 3.3V: 4989.5,3231.35 5003.65,3245.5 5006.13,3243.4 5008.72,3241.9 5011.42,3240.89 5014.25,3240.26 5017.19,3239.92 5020.27,3239.74 5026.85,3239.47 4995.53,3208.15 4995.26,3214.73 4995.08,3217.81 4994.74,3220.75 4994.11,3223.58 4993.1,3226.28 4991.6,3228.87
  region net 15: 3370.57,3937.01 3377.64,3929.94 3375.73,3927.85 3374.27,3925.89 3373.24,3924.03 3372.56,3922.24 3372.21,3920.51 3372.12,3918.79 3372.25,3917.07 3372.56,3915.33 3374.52,3907.52 3374.96,3905.23 3375.28,3902.76 3375.43,3900.07 3375.36,3897.15 3337.78,3934.73 3340.7,3934.8 3343.39,3934.65 3345.86,3934.33 3348.15,3933.9 3355.95,3931.93 3357.7,3931.63 3359.42,3931.49 3361.13,3931.58 3362.87,3931.94 3364.66,3932.61 3366.52,3933.65 3368.48,3935.1
  region net 16: 3570.57,3937.01 3577.64,3929.94 3575.73,3927.85 3574.27,3925.89 3573.24,3924.03 3572.56,3922.24 3572.21,3920.51 3572.12,3918.79 3572.25,3917.07 3572.56,3915.33 3574.52,3907.52 3574.96,3905.23 3575.28,3902.76 3575.43,3900.07 3575.36,3897.15 3537.78,3934.73 3540.7,3934.8 3543.39,3934.65 3545.86,3934.33 3548.15,3933.9 3555.95,3931.93 3557.7,3931.63 3559.42,3931.49 3561.13,3931.58 3562.87,3931.94 3564.66,3932.61 3566.52,3933.65 3568.48,3935.1
  region net 41: 3588.23,5262.64 3588.23,5252.64 3585.4,5252.52 3582.99,5252.16 3580.94,5251.57 3579.2,5250.79 3577.72,5249.81 3576.45,5248.66 3575.32,5247.35 3574.3,5245.9 3570.17,5238.99 3568.87,5237.06 3567.34,5235.09 3565.55,5233.08 3563.43,5231.06 3563.43,5284.21 3565.55,5282.19 3567.34,5280.19 3568.87,5278.22 3570.17,5276.29 3574.3,5269.38 3575.32,5267.93 3576.45,5266.62 3577.72,5265.47 3579.2,5264.49 3580.94,5263.71 3582.99,5263.12 3585.4,5262.76
  region net 11: 6548.33,5665.96 6562.48,5680.11 6565.17,5677.64 6567.75,5675.71 6570.24,5674.27 6572.67,5673.26 6575.06,5672.62 6577.45,5672.31 6579.86,5672.26 6582.31,5672.43 6587.45,5673.18 6593.08,5674.11 6596.15,5674.52 6599.42,5674.8 6602.92,5674.91 6606.67,5674.8 6553.64,5621.77 6553.53,5625.52 6553.64,5629.02 6553.92,5632.29 6554.33,5635.36 6555.26,5640.99 6556.01,5646.13 6556.18,5648.58 6556.13,5650.99 6555.82,5653.38 6555.18,5655.77 6554.17,5658.2 6552.73,5660.69 6550.8,5663.27
  region net 35: 6044.53,4148.43 6051.6,4155.5 6053.55,4153.72 6055.38,4152.36 6057.13,4151.38 6058.81,4150.74 6060.44,4150.39 6062.06,4150.29 6063.68,4150.39 6065.33,4150.65 6072.68,4152.41 6077.14,4153.08 6079.65,4153.22 6082.38,4153.15 6046.88,4117.66 6046.82,4120.38 6046.95,4122.89 6047.62,4127.35 6049.38,4134.7 6049.64,4136.35 6049.74,4137.97 6049.64,4139.59 6049.29,4141.22 6048.65,4142.9 6047.67,4144.65 6046.31,4146.48
  region net 36: 6043.57,4564.36 6042.13,4579.94 6043.91,4578.34 6045.7,4577.07 6047.49,4576.12 6049.31,4575.45 6051.14,4575.03 6053,4574.83 6054.89,4574.84 6056.83,4575 6060.82,4575.73 6065.04,4576.79 6069.52,4577.95 6074.31,4578.99 6048.36,4536.02 6047.93,4537.69 6047.64,4539.45 6047.36,4543.18 6047.34,4551.03 6047.17,4554.86 6046.62,4558.46 6046.14,4560.12 6045.49,4561.67 6044.64,4563.09
  region net 37: 6034.72,4967.38 6034.72,4977.38 6037.36,4977.49 6039.62,4977.83 6041.55,4978.37 6043.19,4979.1 6044.59,4980.01 6045.8,4981.09 6046.88,4982.3 6047.86,4983.66 6051.81,4990.09 6054.49,4993.73 6056.17,4995.59 6058.14,4997.47 6058.14,4947.28 6056.17,4949.16 6054.49,4951.03 6051.81,4954.66 6047.86,4961.09 6046.88,4962.45 6045.8,4963.67 6044.59,4964.74 6043.19,4965.65 6041.55,4966.38 6039.62,4966.92 6037.36,4967.26
  region net 38: 6051.6,5362.94 6044.53,5370.01 6046.31,5371.96 6047.67,5373.79 6048.65,5375.54 6049.29,5377.22 6049.64,5378.85 6049.74,5380.47 6049.64,5382.09 6049.38,5383.74 6047.62,5391.09 6046.95,5395.55 6046.82,5398.06 6046.88,5400.78 6082.38,5365.29 6079.65,5365.22 6077.14,5365.36 6072.68,5366.03 6065.33,5367.78 6063.68,5368.05 6062.06,5368.15 6060.44,5368.05 6058.81,5367.7 6057.13,5367.06 6055.38,5366.08 6053.55,5364.72
  region net 39: 6051.6,5789.25 6044.53,5796.32 6046.31,5798.27 6047.67,5800.1 6048.65,5801.85 6049.29,5803.53 6049.64,5805.16 6049.74,5806.78 6049.64,5808.4 6049.38,5810.05 6047.62,5817.4 6046.95,5821.86 6046.82,5824.37 6046.88,5827.1 6082.38,5791.6 6079.65,5791.54 6077.14,5791.67 6072.68,5792.34 6065.33,5794.1 6063.68,5794.36 6062.06,5794.46 6060.44,5794.36 6058.81,5794.01 6057.13,5793.37 6055.38,5792.4 6053.55,5791.04
  region net 7: 4128.02,5165.1 4135.1,5158.02 4134.35,5157.16 4133.73,5156.17 4132.81,5153.97 4132.25,5151.59 4131.98,5149.25 4119.25,5161.98 4121.59,5162.25 4123.97,5162.81 4126.17,5163.73 4127.16,5164.35
  region net 6: 4035.52,5167.6 4042.6,5160.52 4041.85,5159.66 4041.23,5158.67 4040.31,5156.47 4039.75,5154.09 4039.48,5151.75 4026.75,5164.48 4029.09,5164.75 4031.47,5165.31 4033.67,5166.23 4034.66,5166.85
  region net 1: 4779.01,5066.08 4780.46,5053.38 4779.11,5051.88 4777.74,5050.11 4775.42,5046.53 4769.62,5063.58 4770.78,5063.25 4772.01,5063.14 4773.29,5063.24 4774.57,5063.52 4775.82,5063.97 4777,5064.56 4778.08,5065.27
  region net 15: 3979.48,4897.4 3972.4,4904.48 3973.15,4905.34 3973.77,4906.33 3974.69,4908.53 3975.25,4910.91 3975.52,4913.25 3988.25,4900.52 3985.91,4900.25 3983.53,4899.69 3981.33,4898.77 3980.34,4898.15
  region net 15: 4223.02,5155.1 4230.1,5148.02 4229.35,5147.16 4228.73,5146.17 4227.81,5143.97 4227.25,5141.59 4226.98,5139.25 4214.25,5151.98 4216.59,5152.25 4218.97,5152.81 4221.17,5153.73 4222.16,5154.35
  region net 16: 4638.65,4855 4638.65,4865 4639.79,4865.09 4640.92,4865.34 4643.14,4866.25 4645.21,4867.53 4647.06,4869.01 4647.06,4850.99 4645.21,4852.47 4643.14,4853.75 4640.92,4854.66 4639.79,4854.91
  region net 11: 4888.12,5817.26 4902.16,5803.02 4900.52,5801.26 4899.34,5799.76 4897.76,5797.23 4896.18,5794.7 4894.99,5793.21 4893.34,5791.46 4876.46,5808.54 4878.24,5810.17 4879.74,5811.34 4882.3,5812.89 4884.85,5814.45 4886.35,5815.62
  region net 3.3V: 4955,4870.59 4935,4870.59 4934.91,4873.24 4934.69,4875.74 4934,4880.12 4933.31,4883.34 4932.99,4885 4957.01,4885 4956.69,4883.34 4956,4880.12 4955.31,4875.74 4955.09,4873.24
  region net 42: 5328.56,5663.98 5321.48,5671.06 5322.16,5671.86 5322.6,5672.66 5322.86,5673.48 5322.98,5674.32 5323.02,5678.25 5335.75,5665.52 5331.82,5665.48 5330.98,5665.36 5330.16,5665.1 5329.36,5664.66
  region net 18: 4435.1,5236.98 4428.02,5229.9 4427.16,5230.65 4426.17,5231.27 4423.97,5232.19 4421.59,5232.75 4419.25,5233.02 4431.98,5245.75 4432.25,5243.41 4432.81,5241.03 4433.73,5238.83 4434.35,5237.84
  region net 41: 5106.98,5489.9 5099.9,5496.98 5100.65,5497.84 5101.27,5498.83 5102.19,5501.03 5102.75,5503.41 5103.02,5505.75 5115.75,5493.02 5113.41,5492.75 5111.03,5492.19 5108.83,5491.27 5107.84,5490.65
  region net 41: 5436.35,5510 5436.35,5500 5435.21,5499.91 5434.08,5499.66 5431.86,5498.75 5429.79,5497.47 5427.94,5495.99 5427.94,5514.01 5429.79,5512.53 5431.86,5511.25 5434.08,5510.34 5435.21,5510.09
